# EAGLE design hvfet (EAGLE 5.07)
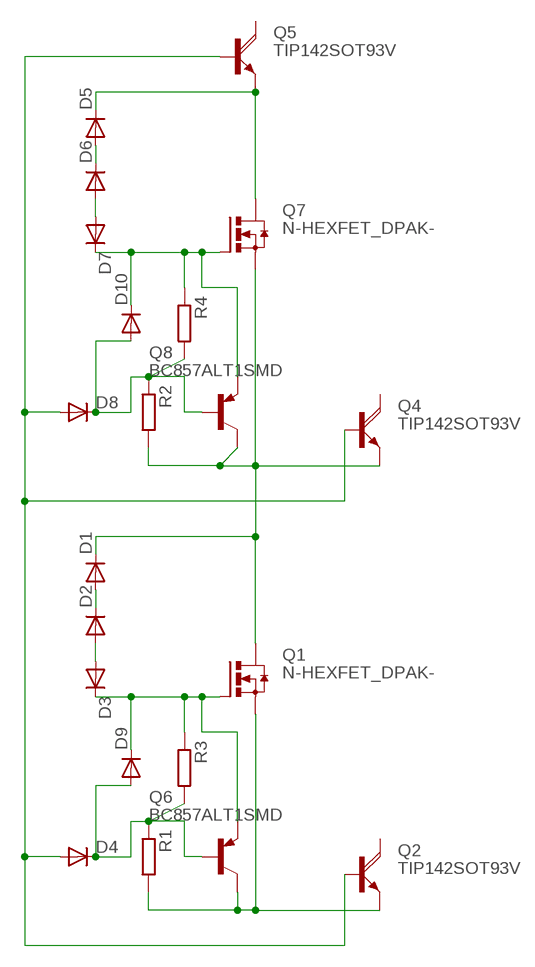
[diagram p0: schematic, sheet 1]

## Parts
D1  DIODE-MINIMELF  [MINIMELF]
D2  DIODE-MINIMELF  [MINIMELF]
D3  DIODE-SMA-DO214  [SMA-DO214AC]
D4  DIODE-SMA-DO214  [SMA-DO214AC]
D5  DIODE-MINIMELF  [MINIMELF]
D6  DIODE-MINIMELF  [MINIMELF]
D7  DIODE-SMA-DO214  [SMA-DO214AC]
D8  DIODE-SMA-DO214  [SMA-DO214AC]
D9  DIODE-SMA-DO214  [SMA-DO214AC]
D10  DIODE-SMA-DO214  [SMA-DO214AC]
Q1  N-HEXFET_DPAK-  [TO252]
Q2  TIP142SOT93V  [SOT93V]
Q4  TIP142SOT93V  [SOT93V]
Q5  TIP142SOT93V  [SOT93V]
Q6  BC857ALT1SMD  [SOT23-BEC]
Q7  N-HEXFET_DPAK-  [TO252]
Q8  BC857ALT1SMD  [SOT23-BEC]
R1  R-EU_R1206  [R1206]
R2  R-EU_R1206  [R1206]
R3  R-EU_R1206  [R1206]
R4  R-EU_R1206  [R1206]

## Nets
BB: D4.A D8.A Q2.B Q4.B Q5.B
D2: D1.C Q1.3(D) Q4.E Q7.2(S) Q8.C R2.2
D3: D5.C Q5.E Q7.3(D)
E1: Q1.2(S) Q2.E Q6.C R1.2
KB1: D4.K(C) D9.A Q6.B R1.1 R3.2
KB2: D8.K(C) D10.A Q8.B R2.1 R4.2
N$2: D1.A D2.C
N$3: D2.A D3.A
N$6: D3.K(C) D9.K(C) Q1.1(G) Q6.E R3.1
N$7: D5.A D6.C
N$8: D6.A D7.A
N$11: D7.K(C) D10.K(C) Q7.1(G) Q8.E R4.1
Unconnected: Q2.C Q4.C Q5.C

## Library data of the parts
D1-D10 = diode:DIODE-: DIODE
Q1 Q7 = transistor-power:N-HEXFET_?-*: HEXFET® Power MOSFET
Q2 Q4 Q5 = transistor-power:TIP142: NPN DARLINGTON TRANSISTOR
Q6 Q8 = transistor-pnp:BC857*: PNP Transistror
R1-R4 = rcl:R-EU_: RESISTOR, European symbol

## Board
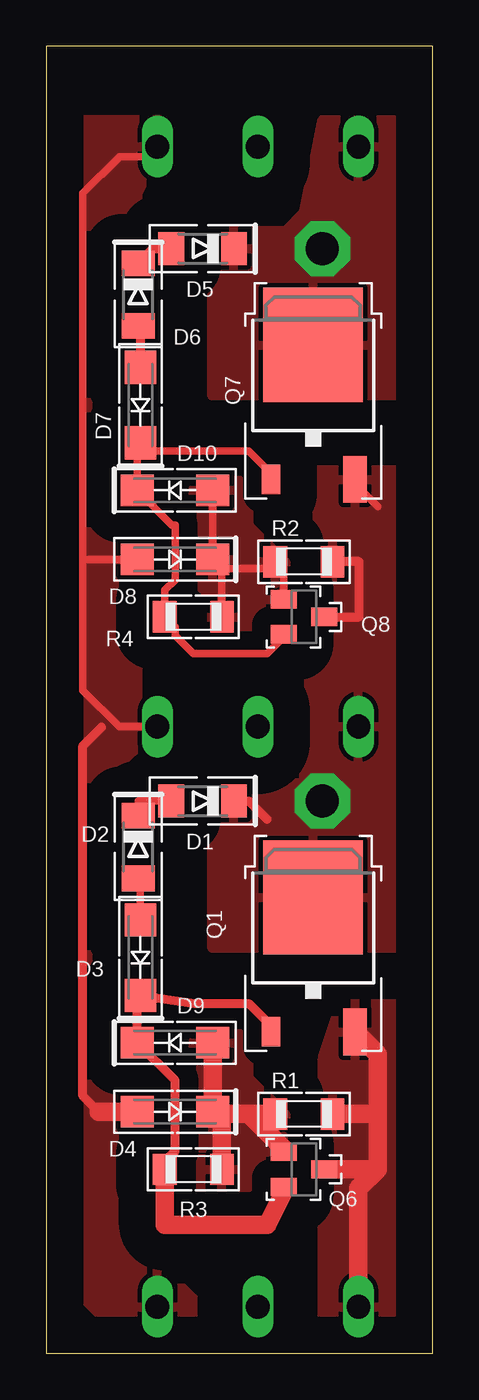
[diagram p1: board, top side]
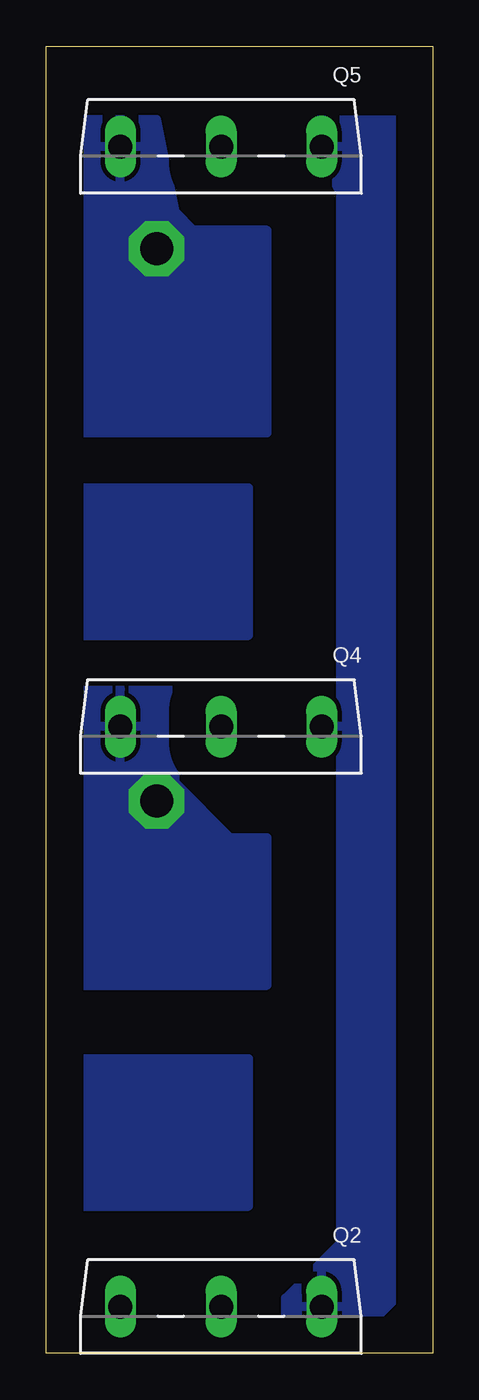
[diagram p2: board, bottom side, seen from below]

Size 21 x 71 mm. Coordinates in mm from the lower left corner, seen from the top.
Outline: 0,0 21,0 21,71 0,71 0,0
Copper layers (1*16): Top 0.035mm / dielectric 1.5mm / Bottom 0.035mm
Design rules "default": minimum track width 10mil, minimum drill 20mil, track to track 8mil, track to pad 8mil, pad to pad 8mil, via to via 8mil, smd to smd 8mil, copper to edge 40mil, drill to drill 8mil, minimum pad ring 1mil, minimum via ring 8mil, stop-mask expansion 4mil, vias tented up to drill 0mil, thermal gap 10mil

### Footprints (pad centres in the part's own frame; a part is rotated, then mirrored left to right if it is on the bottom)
MINIMELF = smd 1.4 x 1.8: A 1.7,0; C -1.7,0
SMA-DO214AC = smd 1.8 x 1.7: A 2.05,-0.127; K -2.05,-0.127
TO252 = smd 1 x 1.6: 1 -2.28,-3.53 | smd 1.27 x 2.54: 2 2.28,-3.53 | smd 5.4 x 6.2: 3 0,3.77
SOT93V = drill 1.3 pad 1.676 long: B -5.461,-2.54; C 0,-2.54; E 5.461,-2.54
SOT23-BEC = smd 1 x 1.4: B -0.95,-1.1; C 0,1.1; E 0.95,-1.1
R1206 = smd 1.3 x 1.7: 1 -1.55,0; 2 1.55,0

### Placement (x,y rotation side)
D1  8.5,30 180 top
D2  5,27.5 270 top
D3  5,21.5 90 top
D4  7,13 180 top
D5  8.5,60 180 top
D6  5,57.5 270 top
D7  5,51.5 90 top
D8  7,43 180 top
D9  7,17 0 top
D10  7,47 0 top
Q1  14.5,21 0 top
Q2  11.5,0 180 bottom
Q4  11.5,31.5 180 bottom
Q5  11.5,63 180 bottom
Q6  14,10 270 top
Q7  14.5,51 0 top
Q8  14,40 270 top
R1  14,13 0 top
R2  14,43 0 top
R3  8,10 0 top
R4  8,40 0 top

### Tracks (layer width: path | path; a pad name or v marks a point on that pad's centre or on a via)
BB
  Top 0.406: Q4.B 3.96,34.04 2,36 2,43 | 2,43 2,63 4,65 5.5,65 Q5.B | D8.A 2.13,43.13 2,43
  Top 0.5: 3,34 2,33 2,14 2.87,13.13
  Top 1: 3.13,13.13 D4.A 2.87,13.13
  pour Top (isolate 2, rank 2): 7,67 2,67 1,66 1,4 5,0 6,0 8,2 8,3 5,6 5,63
  pour Bottom (isolate 2, rank 2): 7,67 2,67 1,66 1,4 5,0 6,0 8,2 8,3 5,6 5,63
D2  (via drill 1.8 pad 3)
  Top 0.406: Q7.2 16.78,47.22 18,46
  Top 0.5: D1.C 11,30 12,29 | Q8.C 17,40 17,43 R2.2
  other vias: 15,30
  pour Bottom (isolate 2): 14,36 19,36 19,20 9,20 9,28 11,28 14,31
  pour Top (isolate 2): 14,48 19,48 19,22 9,22 9,31 14,31
D3  (via drill 1.8 pad 3)
  other vias: 15,60
  pour Top (isolate 2): 15,67 19,67 19,52 9,52 9,61 13,61 14,62
  pour Bottom (isolate 2): 15,67 19,67 19,50 9,50 9,61 13,61 14,62
E1
  Top 1: Q2.E 16.96,8.96 18,10 | 18,10 18,13 | 18,13 18,16.25 Q1.2 | 18,13 R1.2 | 18,10 Q6.C
  pour Top (isolate 2): 16,19 19,19 19,17 19,1 15,1 15,2 15,16
KB1
  Top 1: D4.K D9.A | R3.2 9.55,12.63 D4.K | Q6.B 12.9,11.1 11,13 | 11,13 9.18,13 D4.K | 11,13 R1.1
  pour Top (isolate 1.016, rank 2): 9,18 10,18 11,17 11,15 13,13 13,11 11,9 8,9 8,17
KB2
  Top 0.406: R4.2 9.55,42.63 | 9.55,42.63 D8.K D10.A | 9.55,42.63 12.08,42.63 R2.1 12.9,42.55 Q8.B
  pour Top (isolate 1.016, rank 2): 9,48 10,48 11,47 11,45 13,43 13,41 11,39 9,39 9,41 8,42 8,47
N$1
  pour Bottom (isolate 2, rank 2): 10,16 19,16 19,8 10,8
  pour Bottom (isolate 2, rank 2): 10,47 19,47 19,39 10,39
N$2
  Top 0.406: D2.C 5,30 D1.A
N$3
  Top 0.406: D2.A 5.13,25.3 D3.A
N$6
  Top 0.5: R3.1 6.45,10.45 7,11 7,14.82 D9.K 4.95,19.77 D3.K 8.08,19 11,19 12.22,17.78 Q1.1
  Top 1: Q6.E 13.05,9.05 12,7 6.45,7 R3.1
N$7
  Top 0.5: D5.A 5.8,60 D6.C
N$8
  Top 0.5: D7.A 5.13,55.67 D6.A
N$11
  Top 0.406: Q8.E 12.9,38.9 12,38 8,38 7,39 7,39.45 R4.1 6.45,41.45 7,42 7,45 6.82,45 D10.K 4.95,49 | 4.95,49 4.95,49.77 D7.K | Q7.1 12.22,47.78 11,49 4.95,49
